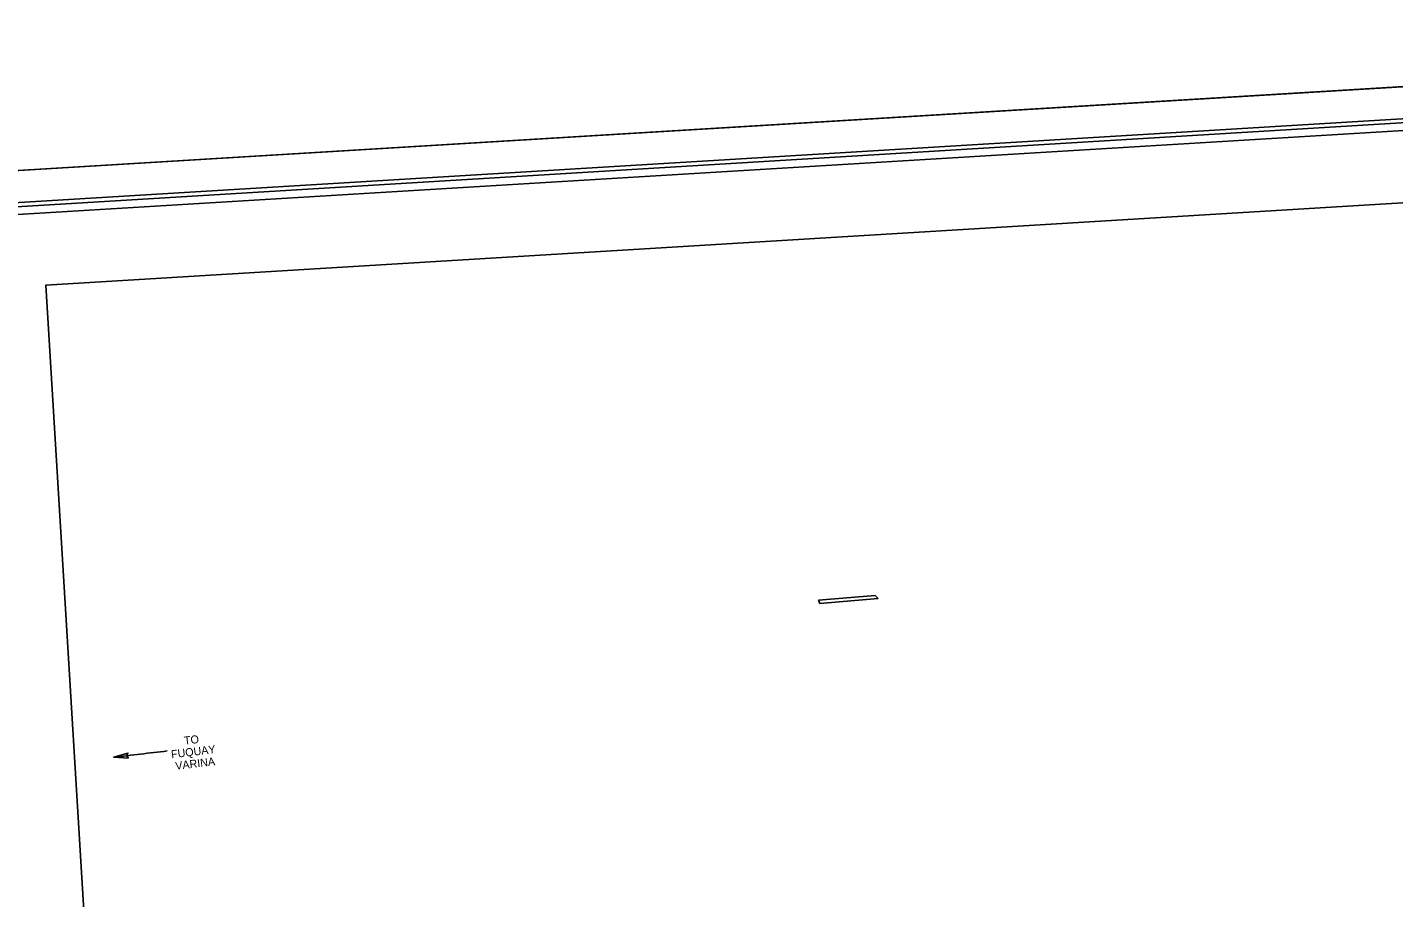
# Model space of a CAD drawing. Extents: x 2110128 to 2112690, y 669500 to 671339.
# Drawn here: x 2110982 to 2111836, y 670290 to 670834 of the extents above; entities that cross this region are included whole.
import ezdxf

# ---------------------------------------------------------------- set-up
doc = ezdxf.new("R2010")
doc.units = 0
for name, color, linetype in [('Default Symbol Cogo Number', 7, 'Continuous'), ('Exist Other Culture Anchor (Guy Wire) CELL', 7, 'Continuous'), ('Exist Roads Curbs', 7, 'Continuous'), ('Exist Roads Curbs Text', 7, 'Continuous'), ('Exist Roads EOP Other Text', 7, 'Continuous'), ('Exist Utilities TV Test Hole SUE LOS A CELL', 7, 'Continuous'), ('Exist Utilities TV Test Hole SUE LOS A Text', 7, 'Continuous'), ('Exist Utilities Water Fire Hydrant CELL', 7, 'Continuous'), ('Exist Utilities Water Fire Hydrant Cogo Number', 7, 'Continuous'), ('Exist Utilities Water Test Hole SUE LOS A Text', 7, 'Continuous')]:
    doc.layers.add(name, color=color, linetype=linetype)

msp = doc.modelspace()

# ---------------------------------------------------------------- linework, layer by layer
at = {"layer": 'Default Symbol Cogo Number'}
for p, q in [((2111511.8, 670478.81), (2111476.46, 670475.84)), ((2111476.46, 670475.84), (2111511.8, 670478.81)), ((2111476.46, 670475.84), (2111477.19, 670473.89)), ((2111476.46, 670475.84), (2111477.19, 670473.89)), ((2111477.19, 670473.89), (2111513.75, 670476.97)), ((2111477.19, 670473.89), (2111513.75, 670476.97)), ((2111511.8, 670478.81), (2111513.75, 670476.97)), ((2111513.75, 670476.97), (2111511.8, 670478.81))]:
    msp.add_line(p, q, dxfattribs=at)
at = {"layer": 'Exist Roads Curbs'}
msp.add_line((2112453.62, 670833.96), (2110773.2, 670732.11), dxfattribs=at)
at = {"layer": 'Exist Roads Curbs Text'}
msp.add_lwpolyline([(2112438.01, 670810.47), (2110940.76, 670719.73), (2111004.28, 669671.65), (2112501.53, 669762.39)], close=True, dxfattribs=at)
at = {"layer": 'Exist Roads EOP Other Text'}
msp.add_lwpolyline([(2110851.21, 669659.87), (2112514.16, 669760.65), (2112450.34, 670813.72), (2110787.39, 670712.94)], close=True, dxfattribs=at)
at = {"layer": 'Exist Utilities TV Test Hole SUE LOS A CELL'}
msp.add_arc((2111734.33, 664668.92), 5751.33, 96.63788, 96.973111, dxfattribs=at)
at = {"layer": 'Exist Utilities TV Test Hole SUE LOS A Text'}
msp.add_lwpolyline([(2111022.58, 670196.24), (2110993.69, 670672.84), (2112191.44, 670745.43), (2112200.05, 670603.34), (2112399.74, 670615.44), (2112420.01, 670280.93)], close=True, dxfattribs=at)
at = {"layer": 'Exist Utilities Water Fire Hydrant CELL'}
msp.add_lwpolyline([(2110944.98, 670715.17), (2112189.1, 670790.57), (2112200.05, 670603.34), (2112399.74, 670615.44), (2112418.35, 670308.36), (2112421.12, 670262.68), (2110980.52, 670175.37)], close=True, dxfattribs=at)
at = {"layer": 'Exist Utilities Water Fire Hydrant Cogo Number'}
msp.add_lwpolyline([(2111045.22, 670377.26), (2111036.1, 670377.71), (2111044.89, 670380.39), (2111043.94, 670378.67)], close=True, dxfattribs=at)
at = {"layer": 'Exist Utilities Water Test Hole SUE LOS A Text'}
msp.add_lwpolyline([(2110839.44, 669639.12), (2112519.86, 669740.96), (2112453.62, 670833.96), (2110773.2, 670732.11)], close=True, dxfattribs=at)

# ---------------------------------------------------------------- texts
at = {"layer": 'Exist Other Culture Anchor (Guy Wire) CELL'}
for s, p in [('TO', (2111080.26, 670385.61)), ('FUQUAY', (2111072.19, 670377.1)), ('VARINA', (2111074.84, 670369.86))]:
    msp.add_text(s, height=5, rotation=6.8055, dxfattribs=at).set_placement(p)

doc.saveas('drawing.dxf')
